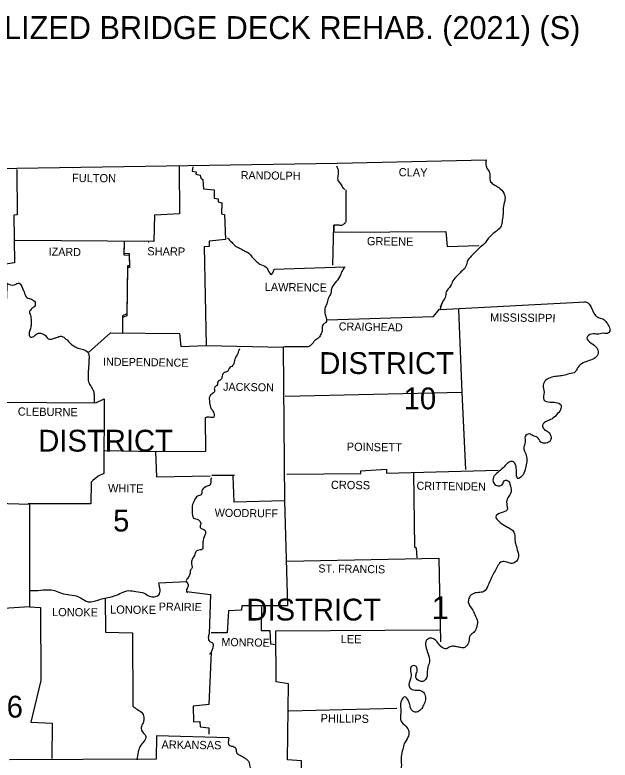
# Model space of a CAD drawing. Extents: x -35254 to 17396, y -8913 to 11592.
# Drawn here: x 14355 to 17396, y 6952 to 10759 of the extents above; entities that cross this region are included whole.
import ezdxf

# ---------------------------------------------------------------- set-up
doc = ezdxf.new("R2010")
doc.units = 0
for name, color, linetype in [('1', 7, 'Continuous'), ('2', 7, 'Continuous'), ('3', 7, 'Continuous'), ('R_Border', 7, 'Continuous')]:
    doc.layers.add(name, color=color, linetype=linetype)

msp = doc.modelspace()

# ---------------------------------------------------------------- linework, layer by layer
at = {"layer": '1'}
for p, q in [((16527.3, 9254.8), (16539, 9291)), ((16530.2, 9266.6), (16542, 9294.9)), ((15361, 8407.5), (15477.5, 8407.5))]:
    msp.add_line(p, q, dxfattribs=at)
for points in [[(11394.6, 9973.9), (12976.6, 9973), (14365, 9975.9), (16002.9, 10001.3), (16762.1, 10019)], [(15193.7, 9984.7), (15195.7, 9742.1), (15068.5, 9735.2), (15064.6, 9602.2), (14357.2, 9606.1)], [(15264.2, 9983.7), (15261.2, 9960.2), (15280.8, 9957.3), (15279.8, 9945.6), (15302.3, 9940.7), (15304.3, 9925), (15315, 9918.2), (15318, 9871.2), (15373.7, 9865.3), (15373.7, 9823.3), (15394.3, 9820.3), (15394.3, 9803.7), (15411.9, 9798.8), (15410.9, 9742.1), (15426.6, 9739.1), (15430.5, 9611), (15347.3, 9603.1), (15348.3, 9575.7), (15322.9, 9574.8), (15331.7, 9069.9), (15726, 9061.1), (15732.8, 8276.4), (15475.5, 8269.6), (15470.6, 8401.6)], [(14365, 9970), (14367, 9737.2), (14350.3, 9736.2), (14353.3, 9492.6), (14284.8, 9482.8), (14290.6, 9417.2), (14314.1, 9386.9), (14312.2, 9309.6), (14179.1, 9304.7), (14174.2, 9185.3), (14052.9, 9181.4), (14047, 9036.6), (14053.9, 9024.9), (14056.8, 8794), (14266.2, 8780.3), (14263.2, 8264.7), (14429.6, 8259.8), (14429.6, 7735.4), (14298.5, 7725.6), (14288.7, 7610.1), (14068.5, 7609.1)], [(16045.9, 9866.3), (16045.9, 9701)], [(15979.4, 9480.8), (15984.3, 9685.3), (15984.3, 9649.1), (16556.6, 9652), (16564.5, 9575.7), (16725.9, 9581.6)], [(14913.9, 9599.2), (14911.9, 9542.5), (14939.3, 9540.5), (14940.3, 9477.9), (14930.5, 9477.9), (14926.6, 9231.3), (14904.1, 9221.6), (14904.1, 9139.4)], [(15036.2, 9597.3), (15037.2, 9598.2)], [(14913.9, 9590.4), (14911.9, 9533.7), (14939.3, 9531.7), (14940.3, 9469.1), (14930.5, 9469.1), (14926.6, 9222.5), (14904.1, 9212.7), (14904.1, 9130.6)], [(15680, 9459.3), (16043, 9472)], [(16527.3, 9254.8), (17269.9, 9293)], [(15950, 9201), (16493, 9218.6), (16525.3, 9255.8)], [(16621.2, 9253.8), (16637.8, 8830.2), (16657.4, 8435.9)], [(14731.9, 9034.7), (14843.4, 9135.5), (15195.7, 9130.6), (15202.5, 9065), (15330.7, 9069.9)], [(15854.1, 9063), (15734.8, 9063), (15726, 9061.1)], [(14266.2, 8780.3), (14769.1, 8777.4), (14812.1, 8797.9), (14809.2, 8415.3), (14779.8, 8402.6), (14753.4, 8380.1), (14744.6, 8371.3), (14743.6, 8261.7), (14423.7, 8261.7)], [(16637.8, 8830.2), (15736.7, 8809.6)], [(15326.8, 8700.1), (15328.7, 8527.9), (15074.3, 8526.9), (14813.1, 8531.8)], [(15074.3, 8526.9), (15078.3, 8398.7), (15353.2, 8403.6)], [(15744.6, 8413.4), (16122.2, 8415.3), (16123.2, 8429), (16254.3, 8438.8), (16254.3, 8418.3), (16823.7, 8433.9)], [(16391.3, 8418.3), (16396.2, 8041.6), (16405, 8035.7), (16407.9, 7984.8)], [(15361, 8390.9), (15356.1, 8389.9)], [(15732.8, 8276.4), (15747.5, 7740.2), (15514.6, 7739.3), (15513.7, 7717.7), (15446.1, 7713.8), (15440.3, 7602.3), (15358.1, 7602.3)], [(15744.6, 7968.2), (16521.4, 7983.9)], [(16521.4, 7983.9), (16529.2, 7555.3)], [(15090, 7856.7), (15231.9, 7863.5)], [(15231.9, 7812.6), (15354.2, 7797), (15347.3, 7597.4)], [(14816, 7780.4), (14818, 7605.2), (14956, 7602.3), (14956.9, 7226.6)], [(14429.6, 7735.4), (14486.3, 7731.4), (14487.3, 7357.7), (14436.4, 7145.4), (14545, 7140.5), (14544.1, 6960.5)], [(15614.4, 7734.4), (15613.5, 7613), (15658.5, 7613), (15660.4, 7545.5), (15688.8, 7542.6)], [(15744.6, 6745.2), (15820.9, 6750.1), (15819.9, 6948.7), (15748.5, 6953.6), (15752.4, 7342), (15690.7, 7350.8), (15688.8, 7612.1), (16523.4, 7617.9)], [(15358.1, 7503.5), (15346.3, 7235.4), (15266.1, 7226.6), (15268.1, 7147.3), (15300.4, 7148.3), (15301.3, 7120.9), (15345.4, 7116), (15346.3, 7083.7)], [(15754.3, 7204.1), (16306.2, 7217.8)], [(15448.1, 7066.1), (15078.3, 7075.9), (15076.3, 6955.6), (14327.8, 6952.6)]]:
    msp.add_lwpolyline(points, dxfattribs=at)
for points in [[(16762.1, 10019), (16767, 9975.9), (16780.7, 9953.4), (16782.6, 9912.3), (16799.3, 9894.7), (16827.7, 9877.1), (16853.1, 9848.7), (16859, 9815.4), (16851.1, 9781.2), (16849.2, 9743), (16845.3, 9709.8), (16839.4, 9679.4), (16815.9, 9655), (16793.4, 9637.4), (16772.9, 9616.8), (16758.2, 9595.3), (16732.7, 9571.8), (16707.3, 9547.4), (16686.8, 9525.8), (16666.2, 9498.4), (16656.4, 9468.1), (16633.9, 9446.6), (16616.3, 9427), (16592.8, 9400.6), (16581.1, 9374.2), (16558.6, 9343.9), (16553.7, 9314.5), (16539, 9291), (16538, 9287.1)], [(15998, 9988.6), (16006.8, 9964.2), (16005.8, 9937.7), (16005.8, 9913.3), (16018.5, 9896.7), (16031.2, 9876.1), (16041, 9867.3)], [(16042, 9698), (16029.3, 9685.3), (16004.8, 9685.3), (15984.3, 9685.3)], [(15441.3, 9619.8), (15462.8, 9597.3), (15481.4, 9578.7), (15502.9, 9567.9), (15528.3, 9553.2), (15550.8, 9541.5), (15565.5, 9522.9), (15586.1, 9502.4), (15606.6, 9485.7), (15638.9, 9470.1), (15649.7, 9453.4), (15664.3, 9432.9), (15680, 9459.3)], [(16040, 9471), (16025.4, 9447.6), (16013.6, 9420.2), (15990.1, 9388.9), (15972.5, 9358.5), (15969.6, 9338), (15955.9, 9310.6), (15948.1, 9283.2), (15939.3, 9259.7), (15939.3, 9235.2), (15946.1, 9210.8), (15944.2, 9188.3), (15929.5, 9177.5), (15925.6, 9149.1), (15919.7, 9129.6), (15907, 9110), (15888.4, 9095.3), (15868.8, 9072.8), (15854.1, 9063)], [(14314.1, 9386.9), (14353.3, 9380.1), (14376.7, 9388.9), (14393.4, 9363.4), (14402.2, 9343.9), (14416.9, 9315.5), (14440.3, 9306.7), (14458, 9291), (14458, 9274.4), (14442.3, 9258.7), (14430.6, 9243.1), (14434.5, 9224.5), (14438.4, 9199), (14438.4, 9174.6), (14432.5, 9152.1), (14427.6, 9131.5), (14432.5, 9113.9), (14451.1, 9116.9), (14470.7, 9131.5), (14491.2, 9131.5), (14510.8, 9120.8), (14531.3, 9102.2), (14551.9, 9106.1), (14568.5, 9111), (14592, 9117.8), (14608.6, 9109), (14623.3, 9097.3), (14640.9, 9078.7), (14657.5, 9067), (14679.1, 9056.2), (14705.5, 9049.4), (14729.9, 9032.7), (14733.9, 9004.3), (14732.9, 8979.9), (14730.9, 8949.6), (14729, 8916.3), (14731.9, 8884), (14742.7, 8862.5), (14756.4, 8837), (14760.3, 8813.6), (14759.3, 8776.4)], [(17259.1, 9292), (17269.9, 9293), (17303.2, 9257.8), (17317.8, 9228.4), (17339.4, 9211.8), (17363.8, 9203), (17382.4, 9180.5), (17395.1, 9156), (17388.3, 9134.5), (17360.9, 9132.5), (17330.6, 9127.6), (17301.2, 9128.6), (17277.7, 9109), (17299.2, 9082.6), (17327.6, 9058.2), (17335.4, 9031.7), (17319.8, 9006.3), (17288.5, 8992.6), (17258.2, 8980.9), (17230.8, 8957.4), (17218, 8934.9), (17187.7, 8925.1), (17156.4, 8916.3), (17129, 8913.4), (17097.7, 8907.5), (17067.4, 8892.8), (17054.6, 8867.4), (17058.6, 8831.2), (17057.6, 8793), (17089.9, 8780.3), (17118.2, 8779.3), (17145.6, 8764.6), (17142.7, 8743.1), (17122.2, 8715.7), (17097.7, 8694.2), (17073.2, 8683.4), (17050.7, 8662.9), (17058.6, 8642.3), (17079.1, 8628.6), (17093.8, 8606.1), (17091.8, 8585.6), (17068.3, 8570.9), (17042.9, 8576.8), (17024.3, 8601.2), (17002.8, 8609.1), (16984.2, 8617.9), (16962.7, 8605.2), (16962.7, 8576.8), (16954.8, 8546.4), (16961.7, 8523.9), (16970.5, 8492.6), (16969.5, 8469.2), (16961.7, 8435.9), (16945.1, 8401.6), (16925.5, 8390.9), (16917.7, 8428.1), (16913.8, 8458.4), (16902, 8476), (16886.4, 8477), (16865.8, 8462.3), (16843.3, 8439.8), (16814.9, 8415.3), (16798.3, 8390.9), (16807.1, 8360.6), (16828.6, 8352.7), (16845.3, 8358.6), (16854.1, 8378.2), (16870.7, 8381.1), (16886.4, 8350.8)], [(15501.9, 9052.3), (15490.2, 9022), (15476.5, 8992.6), (15467.7, 8967.2), (15449.1, 8952.5), (15443.2, 8938.8), (15426.6, 8932.9), (15413.9, 8913.4), (15408, 8895.7), (15394.3, 8887.9), (15387.4, 8866.4), (15374.7, 8854.6), (15375.7, 8835.1), (15361, 8821.4), (15349.3, 8805.7), (15349.3, 8784.2), (15354.2, 8755.8), (15364, 8739.2), (15372.8, 8717.7), (15371.8, 8704), (15347.3, 8704), (15326.8, 8700.1)], [(15356.1, 8389.9), (15351.2, 8357.6), (15332.6, 8348.8), (15311.1, 8327.3), (15306.2, 8307.7), (15288.6, 8299.9), (15272, 8279.3), (15261.2, 8251), (15261.2, 8221.6), (15268.1, 8188.4), (15292.5, 8179.5), (15304.3, 8160), (15302.3, 8139.4), (15325.8, 8125.7), (15329.7, 8114), (15325.8, 8101.3), (15315, 8065.1), (15316, 8040.6), (15314.1, 8029.9), (15287.6, 8023), (15272, 7996.6), (15261.2, 7978), (15257.3, 7953.5), (15260.2, 7935.9), (15252.4, 7922.2), (15249.5, 7901.7), (15239.7, 7884.1), (15230.9, 7867.4), (15240.7, 7847.9), (15237.7, 7834.2), (15231.9, 7812.6), (15236.8, 7805.8)], [(16886.4, 8350.8), (16890.3, 8322.4), (16873.6, 8292.1), (16867.8, 8261.7), (16870.7, 8231.4), (16839.4, 8214.8), (16812, 8195.2), (16827.7, 8171.7), (16857, 8150.2), (16886.4, 8133.6), (16904.9, 8116.9), (16909.8, 8076.8), (16914.7, 8051.4), (16924.5, 8016.2), (16928.4, 7991.7), (16910.8, 7962.3), (16890.3, 7956.5), (16868.7, 7963.3), (16843.3, 7965.3), (16822.8, 7945.7), (16808.1, 7918.3), (16793.4, 7890.9), (16782.6, 7867.4), (16771.9, 7842), (16750.4, 7812.6), (16723.9, 7807.8), (16692.6, 7799.9), (16674, 7778.4), (16677, 7742.2), (16694.6, 7717.7), (16708.3, 7687.4), (16718.1, 7661), (16713.2, 7627.7), (16699.5, 7603.3), (16681.9, 7588.6), (16674, 7557.3), (16661.3, 7533.8), (16649.6, 7526), (16626.1, 7527.9), (16600.7, 7532.8), (16579.1, 7530.9), (16558.6, 7520.1), (16538, 7527), (16516.5, 7550.4), (16498.9, 7568), (16479.3, 7574.9), (16458.8, 7564.1), (16454.9, 7531.8), (16464.7, 7498.6), (16473.5, 7453.6), (16464.7, 7426.2), (16461.7, 7381.2)], [(14431.5, 7817.5), (14486.3, 7819.5), (14540.1, 7821.5), (14574.4, 7811.7), (14613.5, 7798.9), (14659.5, 7793.1), (14691.8, 7780.4), (14729.9, 7760.8), (14778.9, 7769.6), (14817, 7779.4), (14866.9, 7792.1), (14899.2, 7805.8), (14936.4, 7817.5), (14973.6, 7812.6), (15015.6, 7804.8), (15042.1, 7789.2), (15090, 7796), (15090, 7856.7)], [(15347.3, 7597.4), (15343.4, 7577.8), (15351.2, 7557.3), (15364.9, 7550.4), (15366.9, 7530.9), (15362, 7511.3), (15358.1, 7503.5), (15349.3, 7491.7)], [(16461.7, 7381.2), (16439.2, 7352.8), (16406, 7370.4), (16406, 7393.9), (16410.9, 7418.3), (16399.1, 7434), (16378.6, 7427.2), (16378.6, 7396.8), (16376.6, 7367.5), (16370.7, 7325.4), (16384.4, 7312.7), (16415.7, 7308.8), (16438.2, 7302.9), (16451.9, 7280.4), (16451, 7253), (16440.2, 7226.6), (16424.6, 7205.1), (16400.1, 7197.2), (16380.5, 7209.9), (16372.7, 7235.4), (16363.9, 7257.9), (16347.3, 7274.5), (16329.6, 7255.9), (16325.7, 7221.7), (16326.7, 7192.3), (16326.7, 7152.2), (16352.1, 7125.8), (16367.8, 7095.5), (16362.9, 7068.1), (16344.3, 7035.8), (16336.5, 7007.4), (16328.7, 6969.3), (16329.6, 6927.2), (16322.8, 6886.1), (16309.1, 6858.7), (16283.7, 6836.2), (16267, 6821.5), (16253.3, 6806.8), (16246.5, 6777.5), (16241.6, 6756.9), (16223, 6732.5), (16208.3, 6730.5), (16196.6, 6740.3), (16192.7, 6756.9), (16192.7, 6773.6), (16184.8, 6790.2), (16160.4, 6797.1), (16140.8, 6796.1), (16132, 6782.4), (16144.7, 6744.2), (16149.6, 6719.8), (16142.8, 6686.5), (16146.7, 6682.6), (16111.5, 6664), (16083.1, 6661.1), (16059.6, 6654.2), (16037.1, 6639.5), (16026.3, 6618), (16010.7, 6600.4), (15997, 6583.8), (15978.4, 6575.9), (15957.9, 6579.9), (15930.5, 6582.8), (15914.8, 6563.2), (15919.7, 6534.8), (15938.3, 6518.2), (15965.7, 6510.4), (15994.1, 6512.3), (16021.4, 6515.3), (16046.9, 6501.6), (16042, 6475.2), (16017.5, 6462.4), (15981.3, 6458.5), (15952, 6461.5), (15916.8, 6453.6), (15899.1, 6431.1), (15908.9, 6396.9), (15947.1, 6383.2), (15964.7, 6350.9), (15965.7, 6320.6), (15953, 6280.5), (15935.3, 6261.9), (15901.1, 6254), (15874.7, 6249.2), (15870.8, 6204.1), (15859, 6181.6), (15838.5, 6174.8), (15809.1, 6189.5), (15791.5, 6196.3), (15770, 6206.1), (15742.6, 6222.7), (15722.1, 6219.8), (15727.9, 6176.7), (15729.9, 6174.8), (15753.4, 6142.5), (15776.8, 6117.1), (15787.6, 6086.7)], [(14956.9, 7226.6), (14981.4, 7209.9), (15006.8, 7190.4), (15013.7, 7164), (15011.7, 7145.4), (15003.9, 7129.7), (15001.9, 7105.3), (15013.7, 7087.6), (15024.5, 7073), (15013.7, 7046.6), (14995.1, 7022.1), (14985.3, 6994.7), (14978.5, 6953.6)], [(15448.1, 7066.1), (15451, 7026), (15474.5, 7020.1), (15484.3, 7009.4), (15489.2, 6986.9), (15505.8, 6977.1), (15528.3, 6963.4), (15542, 6953.6), (15551.8, 6937.9), (15557.7, 6912.5), (15573.3, 6895.9), (15594.9, 6888.1), (15610.5, 6869.5), (15620.3, 6843), (15636, 6831.3), (15651.6, 6810.8), (15659.4, 6802), (15673.1, 6778.5), (15686.8, 6766.7), (15696.6, 6759.9), (15712.3, 6755), (15731.8, 6742.3), (15744.6, 6722.7), (15744.6, 6708), (15739.7, 6685.5), (15735.8, 6662), (15733.8, 6635.6), (15731.8, 6612.1), (15740.6, 6592.6), (15735.8, 6563.2), (15726, 6547.6), (15725, 6526), (15722.1, 6493.8), (15718.1, 6475.2), (15709.3, 6444.8), (15696.6, 6429.2)]]:
    msp.add_spline(points, degree=3, dxfattribs=at)

# ---------------------------------------------------------------- texts
msp.add_text('1', height=117.4, dxfattribs=at).set_placement((16485.2, 7671.8))
at = {"layer": '2'}
for s, height, rotation, p in [('CLAY', 42.06, 359.2258, (16315.9, 9934.8)), ('FULTON', 42.06, 359.4996, (14646.8, 9905.5)), ('RANDOLPH', 41.09, 359.2583, (15508.8, 9920.1)), ('GREENE', 42.07, 359.2361, (16153.5, 9582.6)), ('IZARD', 41.08, 358.9258, (14527.4, 9529.7)), ('SHARP', 42.06, 359.3905, (15031.3, 9530.7)), ('LAWRENCE', 42.07, 359.2678, (15631.1, 9348.7)), ('MISSISSIPPI', 42.062, 359.3097, (16782.6, 9193.2)), ('CRAIGHEAD', 41.09, 359.1159, (16009.7, 9147.2)), ('INDEPENDENCE', 41.081, 359.2187, (14805.3, 8967.2)), ('JACKSON', 41.08, 359.1352, (15418.7, 8839)), ('CLEBURNE', 42.06, 359.2535, (14369.9, 8711.8)), ('POINSETT', 42.06, 359.1987, (16050.5, 8532.2)), ('CROSS', 42.06, 359.3839, (15969.6, 8337.1)), ('WHITE', 42.07, 359.3139, (14830.7, 8320.4)), ('CRITTENDEN', 41.09, 359.213, (16406.9, 8333.2)), ('WOODRUFF', 41.08, 359.2748, (15375.7, 8195.2)), ('ST. FRANCIS', 41.081, 359.2216, (15905, 7910.5)), ('LONOKE', 42.07, 359.4974, (14545, 7687.4)), ('LONOKE', 42.07, 359.4974, (14841.5, 7700.1)), ('PRAIRIE', 41.09, 359.2116, (15090, 7715.8)), ('LEE', 42.07, 359.4327, (16019.5, 7549.5)), ('MONROE', 41.08, 359.0331, (15409.9, 7534.8)), ('PHILLIPS', 42.06, 359.3179, (15916.8, 7144.4)), ('ARKANSAS', 42.06, 359.2678, (15103.7, 7010.4))]:
    msp.add_text(s, height=height, rotation=rotation, dxfattribs=at).set_placement(p)
at = {"layer": '3'}
for s, height, p in [('DISTRICT', 111.54, (15910.4, 8924.5)), ('10', 111.54, (16341.5, 8744)), ('DISTRICT', 111.54, (14474.6, 8527.9)), ('5', 111.5, (14857.1, 8119.9)), ('DISTRICT', 111.54, (15538.1, 7664.9)), ('DISTRICT 6', 111.54, (13584.2, 7168.9))]:
    msp.add_text(s, height=height, dxfattribs=at).set_placement(p)
at = {"layer": 'R_Border'}
msp.add_text('SPECIALIZED BRIDGE DECK REHAB. (2021) (S)', height=117.24, dxfattribs=at).set_placement((13724.4, 10635.8))

doc.saveas('drawing.dxf')
